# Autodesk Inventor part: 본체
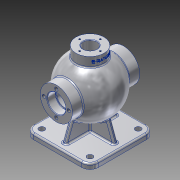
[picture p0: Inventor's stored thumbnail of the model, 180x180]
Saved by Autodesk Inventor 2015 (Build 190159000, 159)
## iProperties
Created: 2025-08
Part Number: 본체
Material: 알루미늄 6061
Document SubType Name: Modeling
Designer: USER
Density: 2.7 g/cm^3
Appearance: 알루미늄 - 평지
Mass: 1517.7 g
Surface Area: 1186.94 cm^2
Volume: 562.113 cm^3
Author: USER
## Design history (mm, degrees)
sketch "스케치1"
  geometry: L1 (-62.5, 62.5)-(62.5, 62.5); L2 (62.5, 62.5)-(62.5, -62.5); L3 (62.5, -62.5)-(-62.5, -62.5); L4 (-62.5, -62.5)-(-62.5, 62.5); L5 (-62.5, 62.5)-(62.5, -62.5); L6 (62.5, 62.5)-(-62.5, -62.5); 1 further point
  constraints: 12 end point, 2 midpoint, 2 parallel, 1 horizontal, 1 perpendicular
  dimensions: "d0" = 125 distance of L2.end L3.end; "d1" = 125 distance of L1.end L2.end
extrude "돌출1" new body sketch "스케치1" distance "d2" = 10; taper "d3" = 0 deg
fillet "모깎기1" dims "d4" = 16
sketch "스케치3"
  geometry: L1 (-4, 50.5)-(4, 50.5); L2 (4, 50.5)-(4, -50.5); L3 (4, -50.5)-(-4, -50.5); L4 (-4, -50.5)-(-4, 50.5); L5 (62.5, 46.5)-(62.5, -46.5) reference; L6 (46.5, -62.5)-(-46.5, -62.5) reference; L7 (-62.5, -46.5)-(-62.5, 46.5) reference; L8 (-46.5, 62.5)-(46.5, 62.5) reference; L9 (-50.5, 4)-(50.5, 4); L10 (50.5, 4)-(50.5, -4); L11 (50.5, -4)-(-50.5, -4); L12 (-50.5, -4)-(-50.5, 4); A1 r 16 centre (46.5, 46.5) between (62.5, 46.5) and (46.5, 62.5) reference; A2 r 16 centre (46.5, -46.5) between (46.5, -62.5) and (62.5, -46.5) reference; A3 r 16 centre (-46.5, -46.5) between (-62.5, -46.5) and (-46.5, -62.5) reference; A4 r 16 centre (-46.5, 46.5) between (-46.5, 62.5) and (-62.5, 46.5) reference; 4 further points
  constraints: 16 end point, 4 parallel, 3 midpoint, 2 horizontal, 2 perpendicular, 2 vertical alignment, 1 horizontal alignment
  dimensions: "d10" = 8 distance of L1.start L1.end; "d11" = 12 distance between parallel lines of L1 L8; "d12" = 12 distance between parallel lines of L6 L3; "d13" = 12 distance between parallel lines of L7 L12; "d14" = 8 distance of L11.end L9.start
extrude "돌출2" join sketch "스케치3" distance "d15" = 50; taper "d16" = 0 deg
sketch "스케치4"
  geometry: L1 (62.5, 10)-(62.5, 0) reference; L2 (62.5, 0)-(-62.5, 0) reference; L3 (-62.5, 0)-(-62.5, 10) reference; L4 (-62.5, 10)-(-50.5, 10) reference; L5 (-50.5, 10)-(-50.5, 60) reference; L6 (-50.5, 60)-(50.5, 60) reference; L7 (50.5, 60)-(50.5, 10) reference; L8 (50.5, 10)-(62.5, 10) reference; L9 (0, 139)-(0, 31); L10 (-4, 60)-(4, 60) reference; A1 r 54 centre (0, 85) between (0, 31) and (0, 139); 3 further points
  constraints: 2 end point, 2 midpoint, 2 point on circle, 1 centre point, 1 perpendicular, 1 vertical alignment
  dimensions: "d18" = 108 diameter of A1; "d19" = 85 distance of point (0, 0) A1.centre
revolve "회전1" sketch "스케치4" stored, may be unused: angle "d20" = 90 deg
node "작업 평면1"
sketch "스케치5"
  geometry: C1 r 31 at (0, 85); 1 further point
  constraints: 1 centre point, 1 vertical alignment
  dimensions: "d22" = 62 diameter of C1; "d23" = 85 distance of point (0, 0) C1.centre
extrude "돌출3" join sketch "스케치5" stored distance "d24" = 50; taper "d25" = 0 deg
node "작업 평면2"
sketch "스케치6"
  geometry: L1 (-4, -47.697)-(-4, -4) reference; L2 (4, -4)-(4, -47.697) reference; L3 (47.697, -4)-(4, -4) reference; L4 (4, 4)-(47.697, 4) reference; L5 (4, 44.215)-(4, 4) reference; L6 (4, 44.215)-(-4, 44.215) reference; L7 (-4, 4)-(-4, 44.215) reference; L8 (-47.697, 4)-(-4, 4) reference; L9 (-4, -4)-(-47.697, -4) reference; L10 (50.5, 4)-(50.5, -4) reference; L11 (50.5, -4)-(4, -4) reference; L12 (4, -4)-(4, -50.5) reference; L13 (4, -50.5)-(-4, -50.5) reference; L14 (-4, -50.5)-(-4, -4) reference; L15 (-4, -4)-(-50.5, -4) reference; L16 (-50.5, -4)-(-50.5, 4) reference; L17 (-50.5, 4)-(-4, 4) reference; L18 (-4, 4)-(-4, 50.5) reference; L19 (-4, 50.5)-(4, 50.5) reference; L20 (4, 50.5)-(4, 4) reference; L21 (4, 4)-(50.5, 4) reference; L22 (-62.5, 46.5)-(-62.5, -46.5) reference; L23 (-46.5, -62.5)-(46.5, -62.5) reference; L24 (62.5, -46.5)-(62.5, 46.5) reference; L25 (46.5, 62.5)-(-46.5, 62.5) reference; C1 r 27 at (0, 0); A1 r 47.864 centre (0, 0) between (-4, -47.697) and (4, -47.697) reference; A2 r 47.864 centre (0, 0) between (47.697, -4) and (47.697, 4) reference; A3 r 47.864 centre (0, 0) between (-47.697, 4) and (-47.697, -4) reference; A4 r 54 centre (0, 0) between (-31, 44.215) and (31, 44.215) reference; A5 r 16 centre (-46.5, 46.5) between (-46.5, 62.5) and (-62.5, 46.5) reference; A6 r 16 centre (-46.5, -46.5) between (-62.5, -46.5) and (-46.5, -62.5) reference; A7 r 16 centre (46.5, -46.5) between (46.5, -62.5) and (62.5, -46.5) reference; A8 r 16 centre (46.5, 46.5) between (62.5, 46.5) and (46.5, 62.5) reference; 1 further point
  constraints: 1 centre point, 1 coincident
  dimensions: "d27" = 54 diameter of C1
extrude "돌출4" join sketch "스케치6" stored distance "d28" = 50; taper "d29" = 0 deg
hole "구멍1" diameter "d34" = 30; stored, may be unused: countersink angle "d38" = 90 deg, drill point angle "d40" = 0 deg; dims "d35" = 6, "d36" = 35, "d37" = 16, "d39" = 31.5, "d43" = 10, "d44" = 10
sketch "스케치8"
  geometry: L1 (65, 54)-(50.5, 54) reference; L2 (50.5, 54)-(50.5, 10) reference; L3 (50.5, 10)-(62.5, 10) reference; L4 (62.5, 10)-(62.5, 0) reference; L5 (62.5, 0)-(-62.5, 0) reference; L6 (-62.5, 0)-(-62.5, 10) reference; L7 (-62.5, 10)-(-50.5, 10) reference; L8 (-50.5, 10)-(-50.5, 60) reference; L9 (-50.5, 60)-(-47.864, 60) reference; L10 (-27, 131.765)-(-27, 150) reference; L11 (-27, 150)-(27, 150) reference; L12 (27, 150)-(27, 131.765) reference; L13 (44.215, 116)-(65, 116) reference; L14 (65, 116)-(65, 102.5) reference; L15 (49, 100)-(33.5, 100) reference; L16 (33.5, 100)-(33.5, 70) reference; L17 (33.5, 70)-(49, 70) reference; L18 (65, 67.5)-(65, 54) reference; L19 (0, 129)-(0, 41); L20 (65, 102.5)-(49, 102.5) reference; L21 (49, 102.5)-(49, 100) reference; L22 (49, 70)-(49, 67.5) reference; L23 (49, 67.5)-(65, 67.5) reference; A1 r 54 centre (0, 85) between (-27, 131.765) and (-47.864, 60) reference; A2 r 54 centre (0, 85) between (44.215, 116) and (27, 131.765) reference; A3 r 44 centre (0, 85) between (0, 129) and (0, 41); 3 further points
  constraints: 2 end point, 2 midpoint, 2 point on circle, 1 centre point, 1 coincident, 1 vertical, 1 vertical alignment
  dimensions: "d41" = 88 diameter of A3
revolve "회전3" sketch "스케치8" stored, may be unused: angle "d42" = 90 deg
hole "구멍2" diameter "d47" = 26; stored, may be unused: countersink angle "d51" = 90 deg, drill point angle "d53" = 0 deg; dims "d45" = 10, "d46" = 10, "d48" = 6, "d49" = 35, "d50" = 16, "d52" = 26
feature "면 기울기3" dims angle "d56" = 20 deg
hole "구멍3" diameter "d59" = 11; stored, may be unused: countersink angle "d63" = 90 deg, drill point angle "d65" = 0 deg; dims "d57" = 10, "d58" = 10, "d60" = 6, "d61" = 35, "d62" = 16, "d64" = 11
sketch "스케치9"
  geometry: L1 (0, 0)-(0, 85); L2 (0, 0)-(-24, 0); C1 r 31 at (0, 0) reference
  constraints: 4 end point, 1 horizontal, 1 vertical
  dimensions: "d72" = 24 distance of L1.start L2.end
hole "구멍4" sketch "스케치9" at (-24, 0) diameter "d73" = 6.647; stored, may be unused: countersink angle "d77" = 90 deg, drill point angle "d79" = 118 deg; dims "d74" = 12, "d75" = 35, "d76" = 16, "d78" = 15
sketch "스케치10"
  geometry: 2 further points
  constraints: 1 horizontal alignment
  dimensions: "d83" = 20 distance of point (0, 0) point (20, 0)
hole "구멍5" sketch "스케치10" at (20, 0) diameter "d84" = 3.242; stored, may be unused: countersink angle "d88" = 90 deg, drill point angle "d90" = 118 deg; dims "d85" = 9, "d86" = 35, "d87" = 16, "d89" = 11
node "작업 평면3"
sketch "스케치12"
  geometry: C1 r 31 at (0, 85); 1 further point
  constraints: 1 centre point, 1 vertical alignment
  dimensions: "d95" = 62 diameter of C1; "d96" = 85 distance of point (0, 0) C1.centre
extrude "돌출5" join sketch "스케치12" stored distance "d97" = 50; taper "d98" = 0 deg
sketch "스케치13"
  geometry: L1 (-27, 150)-(27, 150) reference; L2 (-27, 131.765)-(27, 131.765) reference; L3 (-27, 150)-(27, 150) reference; L4 (-27, 150)-(-27, 131.765) reference; L5 (-27, 131.765)-(27, 131.765) reference; L6 (27, 150)-(27, 131.765) reference; 3 further points
  constraints: 1 midpoint, 1 vertical alignment, 1 other
  dimensions: "d99" = 9 distance from line of L1 point (0, 141)
feature "엠보싱1" sketch "스케치13" dims "d0" = 125, "d1" = 125, "d12" = 12, "d100" = 0.5, "d101" = 0
chamfer "모따기2" distance "d105" = 1; stored, may be unused: second distance "d106" = 2, angle "d107" = 45 deg
fillet "모깎기2" dims "d114" = 3
fillet "모깎기3" dims "d115" = 3
fillet "모깎기4" dims "d116" = 3
chamfer "모따기5" distance "d117" = 1; stored, may be unused: second distance "d118" = 2, angle "d119" = 45 deg
fillet "모깎기5" dims "d120" = 0.6
fillet "모깎기6" dims "d121" = 3
node "솔리드1"
pattern_linear "직사각형 패턴1" dims "d68" = 93, "d71" = 93
pattern_circular "원형 패턴1" dims angle "d81" = 360 deg
pattern_circular "원형 패턴2" dims angle "d92" = 360 deg
mirror "대칭2"
node "투영된 루프1"
node "투영된 루프2"
node "투영된 루프3"
node "절단 모서리 투영2"
node "절단 모서리 투영3"
node "절단 모서리 투영5"
other parameters: "d21" = 65, "d94" = -65
